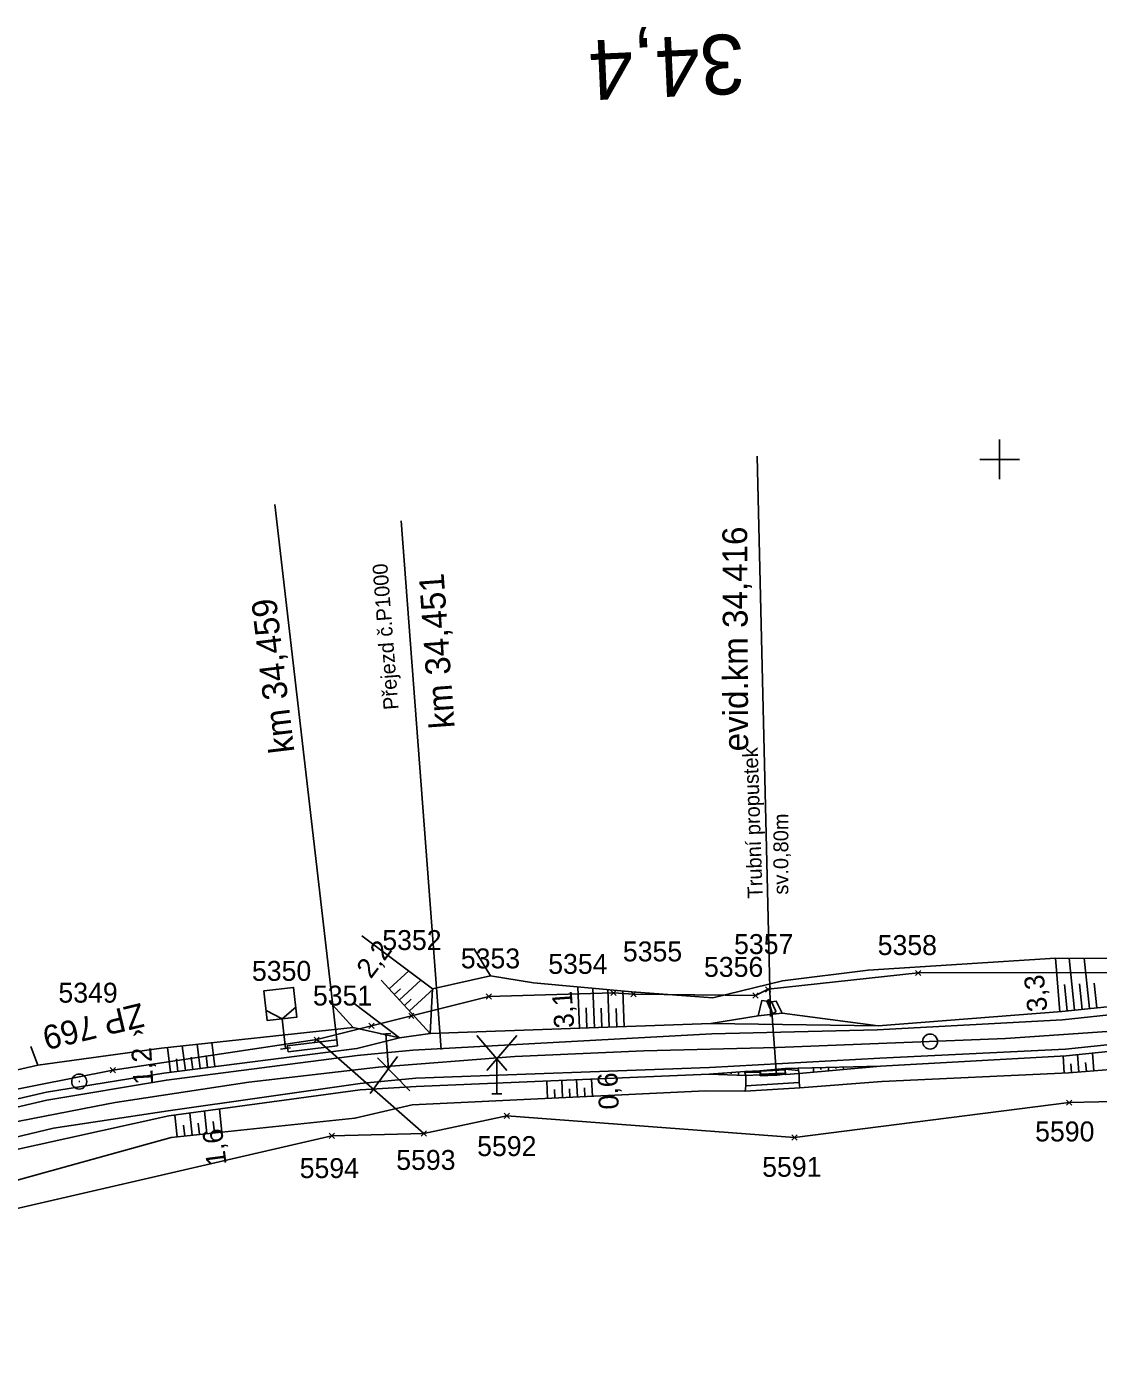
# Model space of a CAD drawing. Extents: x -805730 to -804640, y -1150889 to -1150366.
# Drawn here: x -805297.6 to -805190.1, y -1150691.7 to -1150556.6 of the extents above; entities that cross this region are included whole.
import ezdxf

# ---------------------------------------------------------------- set-up
doc = ezdxf.new("R2010")
doc.units = 0
for name, color, linetype in [('0381KM032-037P - Vrstva 1', 7, 'Continuous'), ('0381KM032-037P - Vrstva 17', 7, 'Continuous'), ('0381KM032-037P - Vrstva 19', 7, 'Continuous'), ('0381KM032-037P - Vrstva 4', 7, 'Continuous'), ('0381KM032-037P - Vrstva 48', 7, 'Continuous'), ('0381KM032-037P - Vrstva 49', 7, 'Continuous'), ('0381KM032-037P - Vrstva 51', 7, 'Continuous'), ('0381KM032-037P - Vrstva 55', 7, 'Continuous'), ('0381KM032-037P - Vrstva 7', 7, 'Continuous'), ('0381KM032-037P - Vrstva 9', 7, 'Continuous'), ('krizky_1000 - Vrstva 1', 7, 'Continuous'), ('szdc - hran DP', 7, 'Continuous'), ('szdc - szdc_cislo', 7, 'Continuous'), ('szdc - szdc_krizek', 7, 'Continuous'), ('vyt_sit - ohrožené', 7, 'Continuous')]:
    doc.layers.add(name, color=color, linetype=linetype)

msp = doc.modelspace()

# ---------------------------------------------------------------- linework, layer by layer
at = {"layer": '0381KM032-037P - Vrstva 1'}
for points in [[(-805182.79, -1150656.72), (-805189.2, -1150657.4), (-805199.42, -1150658.12), (-805222.35, -1150659), (-805235.71, -1150659.34), (-805248.65, -1150659.92), (-805262.34, -1150660.99)], [(-805262.34, -1150660.99), (-805275.34, -1150662.5), (-805288.75, -1150664.54), (-805289.64, -1150664.68), (-805304.6, -1150667.62), (-805306.42, -1150668.06)]]:
    msp.add_lwpolyline(points, dxfattribs=at)
at = {"layer": '0381KM032-037P - Vrstva 17'}
for points in [[(-805070.8, -1150598.9), (-805121.06, -1150638.84), (-805152.76, -1150646.7), (-805170.92, -1150650.08), (-805194.39, -1150650.05), (-805213.2, -1150651.26), (-805221.79, -1150652.33), (-805228.79, -1150654.03)], [(-805228.79, -1150654.03), (-805236.91, -1150653.41), (-805246.77, -1150652.51), (-805251.08, -1150651.83), (-805252.77, -1150649.08)], [(-805266.94, -1150654.72), (-805264.88, -1150657), (-805284.09, -1150659.06), (-805296.52, -1150660.78), (-805297.22, -1150658.9)]]:
    msp.add_lwpolyline(points, dxfattribs=at)
at = {"layer": '0381KM032-037P - Vrstva 19'}
for p, q in [((-805224.33, -1150599.68), (-805223.01, -1150655.91)), ((-805222.9, -1150655.44), (-805223.36, -1150654.35)), ((-805222.89, -1150654.41), (-805222.49, -1150655.3)), ((-805223.99, -1150661.38), (-805221.54, -1150661.24)), ((-805221.51, -1150661.18), (-805221.49, -1150661.72)), ((-805225.47, -1150661.83), (-805224.04, -1150661.74)), ((-805224.04, -1150661.49), (-805224.04, -1150661.74)), ((-805221.51, -1150661.6), (-805224, -1150661.7)), ((-805224, -1150661.7), (-805224, -1150661.8)), ((-805224, -1150661.8), (-805221.51, -1150661.7)), ((-805221.51, -1150661.7), (-805221.51, -1150661.6))]:
    msp.add_line(p, q, dxfattribs=at)
msp.add_lwpolyline([(-805224.22, -1150655.82), (-805223.87, -1150654.3), (-805223.36, -1150654.35), (-805223.23, -1150654.21), (-805222.89, -1150654.41), (-805222.41, -1150654.36), (-805221.82, -1150655.55)], close=True, dxfattribs=at)
for points in [[(-805223.23, -1150654.21), (-805222.87, -1150655.41), (-805222.4, -1150661.78)], [(-805225.57, -1150661.42), (-805224.05, -1150661.35), (-805223.99, -1150661.38)], [(-805225.56, -1150661.53), (-805224.04, -1150661.49), (-805224.05, -1150661.35)], [(-805221.51, -1150661.7), (-805221.51, -1150661.69), (-805221.54, -1150661.24), (-805221.52, -1150661.12), (-805220.23, -1150661.07), (-805220.19, -1150661.33), (-805220.13, -1150661.62)], [(-805220.19, -1150661.33), (-805221.51, -1150661.18), (-805221.52, -1150661.12)], [(-805225.57, -1150661.42), (-805225.56, -1150661.53), (-805225.47, -1150661.83), (-805225.46, -1150662.84), (-805225.54, -1150663.4), (-805220.04, -1150663.05), (-805220.11, -1150662.52), (-805225.46, -1150662.84)], [(-805224, -1150661.7), (-805224.04, -1150661.74), (-805224.02, -1150661.84), (-805223.26, -1150661.81), (-805222.4, -1150661.78)], [(-805223.99, -1150661.81), (-805224, -1150661.8)], [(-805223.99, -1150661.38), (-805223.99, -1150661.81), (-805221.51, -1150661.69)], [(-805222.4, -1150661.78), (-805221.56, -1150661.7), (-805221.49, -1150661.72)], [(-805220.11, -1150662.52), (-805220.13, -1150661.62), (-805221.49, -1150661.72), (-805221.51, -1150661.6)]]:
    msp.add_lwpolyline(points, dxfattribs=at)
for centre, major_axis, ratio, start_param, end_param in [((-805222.69, -1150655.38), (0.215, 0.047), 0.800066, 3.235081, 6.495155), ((-805222.47, -1150661.77), (-0.4, -0.017), 0.197294, 3.17264, 6.315874), ((-805222.47, -1150661.77), (0.4, 0.019), 0.014453, 3.164337, 6.322931)]:
    msp.add_ellipse(centre, major_axis=major_axis, ratio=ratio, start_param=start_param, end_param=end_param, dxfattribs=at)
at = {"layer": '0381KM032-037P - Vrstva 4'}
for p, q in [((-805260.04, -1150606.16), (-805256.03, -1150659.22)), ((-805261.09, -1150657.61), (-805262.09, -1150657.68)), ((-805261.59, -1150657.65), (-805261.34, -1150661.14)), ((-805252.46, -1150657.82), (-805249.46, -1150661.32)), ((-805251.46, -1150661.32), (-805248.46, -1150657.82)), ((-805260.43, -1150659.92), (-805263.17, -1150663.62)), ((-805262.34, -1150660.99), (-805248.65, -1150659.92)), ((-805259.18, -1150663.34), (-805262.42, -1150660.06)), ((-805250.46, -1150663.67), (-805250.46, -1150660.17)), ((-805250.96, -1150663.67), (-805249.96, -1150663.67))]:
    msp.add_line(p, q, dxfattribs=at)
for points in [[(-805097.6, -1150634.39), (-805112.1, -1150639.75), (-805119.36, -1150642.27), (-805152.08, -1150650.89), (-805169.94, -1150653.7), (-805193.71, -1150656.24), (-805212.28, -1150657.22)], [(-805096.44, -1150637.01), (-805110.9, -1150642.46), (-805118.26, -1150644.98), (-805151.42, -1150653.61), (-805169.41, -1150656.67), (-805193.4, -1150659.17), (-805212.01, -1150660.08)], [(-805134.98, -1150644.55), (-805152.23, -1150649.93), (-805170.06, -1150652.94), (-805193.76, -1150655.4), (-805212.2, -1150656.84), (-805228.99, -1150656.61)], [(-805134.56, -1150650.98), (-805151.31, -1150654.12), (-805169.36, -1150657.36), (-805193.31, -1150659.84), (-805211.96, -1150660.88), (-805220.23, -1150661.07)], [(-805228.99, -1150656.61), (-805257.13, -1150657.62), (-805260.23, -1150658.03), (-805264.49, -1150659.11), (-805283.86, -1150661.58), (-805295.64, -1150663.5), (-805324.06, -1150670.09), (-805365.63, -1150680.4), (-805372.09, -1150681.89), (-805381.91, -1150683.24), (-805417.14, -1150687.42), (-805420, -1150686.97)], [(-805212.28, -1150657.22), (-805228.89, -1150657.63), (-805258.88, -1150659.27), (-805264.46, -1150659.8), (-805283.61, -1150662.28), (-805295.6, -1150664.3), (-805323.97, -1150670.91), (-805365.39, -1150681.52), (-805371.9, -1150683.14), (-805381.67, -1150685.01), (-805417.27, -1150688.09), (-805420, -1150686.97)], [(-805212.01, -1150660.08), (-805229.13, -1150661), (-805258.58, -1150662.1), (-805264.18, -1150662.62), (-805283.43, -1150665.36), (-805294.93, -1150667.11), (-805323.21, -1150673.86), (-805364.72, -1150684.28), (-805371.95, -1150685.67), (-805381.73, -1150687.49), (-805401.63, -1150689.36), (-805419.33, -1150691.07), (-805419.49, -1150691.68)], [(-805225.57, -1150661.42), (-805229.16, -1150661.68), (-805258.55, -1150662.93), (-805264.16, -1150663.27), (-805283.37, -1150665.88), (-805323.33, -1150674.68), (-805364.37, -1150685.33), (-805371.95, -1150687.26), (-805381.71, -1150688.97), (-805419.49, -1150691.68)]]:
    msp.add_lwpolyline(points, dxfattribs=at)
at = {"layer": '0381KM032-037P - Vrstva 48'}
for p, q in [((-805193.97, -1150655.42), (-805194.39, -1150650.05)), ((-805192.48, -1150655.27), (-805193.02, -1150650.05)), ((-805190.99, -1150655.11), (-805191.51, -1150650.05)), ((-805261.25, -1150653.12), (-805259.3, -1150651.33)), ((-805260.75, -1150653.68), (-805260.13, -1150653.11)), ((-805260.24, -1150654.23), (-805258.08, -1150652.25)), ((-805259.22, -1150655.33), (-805256.81, -1150653.11)), ((-805242.17, -1150657.08), (-805242.32, -1150652.92)), ((-805240.67, -1150657.03), (-805240.81, -1150653.06)), ((-805239.17, -1150656.98), (-805239.31, -1150653.2)), ((-805193.23, -1150655.34), (-805193.5, -1150652.7)), ((-805191.73, -1150655.19), (-805192, -1150652.62)), ((-805190.24, -1150655.03), (-805190.5, -1150652.54)), ((-805259.73, -1150654.78), (-805259.05, -1150654.16)), ((-805237.67, -1150656.92), (-805237.8, -1150653.33)), ((-805241.42, -1150657.06), (-805241.49, -1150655.02)), ((-805239.92, -1150657), (-805239.99, -1150655.06)), ((-805238.42, -1150656.95), (-805238.49, -1150655.11)), ((-805278.74, -1150660.93), (-805279.04, -1150658.52)), ((-805283.2, -1150661.49), (-805283.52, -1150659)), ((-805281.71, -1150661.3), (-805282.03, -1150658.84)), ((-805280.97, -1150661.21), (-805281.12, -1150659.98)), ((-805280.22, -1150661.11), (-805280.54, -1150658.68)), ((-805279.48, -1150661.02), (-805279.64, -1150659.81)), ((-805193.54, -1150661.57), (-805193.62, -1150659.86)), ((-805192.05, -1150661.47), (-805192.19, -1150659.72)), ((-805190.55, -1150661.35), (-805190.69, -1150659.57)), ((-805282.46, -1150661.4), (-805282.61, -1150660.16)), ((-805218.69, -1150661.03), (-805218.68, -1150661.49)), ((-805217.94, -1150661.02), (-805217.94, -1150661.22)), ((-805217.19, -1150661), (-805217.18, -1150661.35)), ((-805216.44, -1150660.98), (-805216.44, -1150661.13)), ((-805215.69, -1150660.96), (-805215.68, -1150661.22)), ((-805192.79, -1150661.53), (-805192.86, -1150660.66)), ((-805191.3, -1150661.41), (-805191.37, -1150660.53)), ((-805245.37, -1150664.11), (-805245.45, -1150662.37)), ((-805243.87, -1150664.03), (-805243.95, -1150662.31)), ((-805242.37, -1150663.96), (-805242.45, -1150662.25)), ((-805240.87, -1150663.89), (-805240.95, -1150662.18)), ((-805227.71, -1150661.57), (-805227.7, -1150661.74)), ((-805226.96, -1150661.52), (-805226.95, -1150661.64)), ((-805226.21, -1150661.47), (-805226.19, -1150661.8)), ((-805244.62, -1150664.07), (-805244.66, -1150663.21)), ((-805243.12, -1150664), (-805243.16, -1150663.14)), ((-805241.62, -1150663.93), (-805241.66, -1150663.07)), ((-805279.55, -1150667.65), (-805279.78, -1150665.39)), ((-805278.05, -1150667.5), (-805278.3, -1150665.19)), ((-805282.53, -1150667.97), (-805282.76, -1150665.8)), ((-805281.04, -1150667.81), (-805281.27, -1150665.6)), ((-805280.29, -1150667.73), (-805280.41, -1150666.61)), ((-805278.8, -1150667.58), (-805278.92, -1150666.44)), ((-805281.78, -1150667.89), (-805281.9, -1150666.79))]:
    msp.add_line(p, q, dxfattribs=at)
at = {"layer": '0381KM032-037P - Vrstva 49'}
for p, q in [((-805257.13, -1150657.62), (-805262.06, -1150652.24)), ((-805256.9, -1150653.13), (-805257.13, -1150657.62)), ((-805220.23, -1150661.07), (-805211.96, -1150660.88)), ((-805224.04, -1150661.74), (-805225.47, -1150661.83))]:
    msp.add_line(p, q, dxfattribs=at)
for points in [[(-805070.8, -1150598.9), (-805121.06, -1150638.84), (-805152.76, -1150646.7), (-805170.92, -1150650.08), (-805194.39, -1150650.05), (-805213.2, -1150651.26), (-805221.79, -1150652.33), (-805228.79, -1150654.03)], [(-805134.98, -1150644.55), (-805152.23, -1150649.93), (-805170.06, -1150652.94), (-805193.76, -1150655.4), (-805212.2, -1150656.84), (-805221.82, -1150655.55)], [(-805228.79, -1150654.03), (-805236.91, -1150653.41), (-805246.77, -1150652.51), (-805251.08, -1150651.83), (-805256.9, -1150653.13), (-805263.99, -1150647.81)], [(-805134.43, -1150652.2), (-805150.83, -1150656.03), (-805168.82, -1150659.61), (-805193.05, -1150661.55), (-805211.83, -1150662.42), (-805220.04, -1150663.05)], [(-805151.31, -1150654.12), (-805169.36, -1150657.36), (-805193.31, -1150659.84), (-805211.96, -1150660.88), (-805220.13, -1150661.62)], [(-805221.82, -1150655.55), (-805224.22, -1150655.82), (-805228.99, -1150656.61), (-805257.13, -1150657.62)], [(-805296.52, -1150660.78), (-805284.09, -1150659.06), (-805264.88, -1150657), (-805260.23, -1150658.03)], [(-805257.13, -1150657.62), (-805260.23, -1150658.03), (-805264.49, -1150659.11)], [(-805420, -1150686.97), (-805417.14, -1150687.42), (-805381.91, -1150683.24), (-805372.09, -1150681.89), (-805365.63, -1150680.4), (-805324.06, -1150670.09), (-805295.64, -1150663.5), (-805283.86, -1150661.58), (-805264.49, -1150659.11)], [(-805296.52, -1150660.78), (-805324.89, -1150667.28), (-805344.39, -1150673.21)], [(-805220.23, -1150661.07), (-805221.52, -1150661.12), (-805224.05, -1150661.35), (-805225.57, -1150661.42), (-805229.16, -1150661.68)], [(-805372.13, -1150688.5), (-805323.33, -1150674.68), (-805283.37, -1150665.88), (-805264.16, -1150663.27), (-805258.55, -1150662.93), (-805229.16, -1150661.68), (-805225.47, -1150661.83)], [(-805224.04, -1150661.74), (-805224.02, -1150661.84), (-805223.26, -1150661.81), (-805222.4, -1150661.78), (-805221.56, -1150661.7)], [(-805221.56, -1150661.7), (-805221.49, -1150661.72), (-805220.13, -1150661.62)], [(-805229.52, -1150663.36), (-805258.94, -1150664.75), (-805264.69, -1150666.1), (-805283.13, -1150668.03), (-805332.88, -1150681.81), (-805363.18, -1150690.85)], [(-805229.52, -1150663.36), (-805225.54, -1150663.4), (-805220.04, -1150663.05)]]:
    msp.add_lwpolyline(points, dxfattribs=at)
at = {"layer": '0381KM032-037P - Vrstva 51'}
msp.add_line((-805264.77, -1150654.58), (-805260.23, -1150658.03), dxfattribs=at)
msp.add_lwpolyline([(-805262.06, -1150652.24), (-805257.13, -1150657.62), (-805260.23, -1150658.03)], dxfattribs=at)
at = {"layer": '0381KM032-037P - Vrstva 55'}
msp.add_line((-805268.53, -1150658.22), (-805257.77, -1150667.64), dxfattribs=at)
at = {"layer": '0381KM032-037P - Vrstva 7'}
for p, q in [((-805272, -1150656.13), (-805271.65, -1150659.11)), ((-805272.15, -1150659.17), (-805271.16, -1150659.05))]:
    msp.add_line(p, q, dxfattribs=at)
for points in [[(-805272, -1150656.13), (-805270.51, -1150655.96), (-805270.85, -1150652.98), (-805273.83, -1150653.32), (-805273.49, -1150656.3), (-805272, -1150656.13)], [(-805273.6, -1150655.31), (-805272, -1150656.13), (-805270.62, -1150654.96)]]:
    msp.add_lwpolyline(points, dxfattribs=at)
msp.add_circle((-805206.98, -1150658.41), 0.75, dxfattribs=at)
at = {"layer": '0381KM032-037P - Vrstva 9'}
for p, q in [((-805266.48, -1150658.55), (-805272.73, -1150604.53)), ((-805266.52, -1150658.25), (-805271.48, -1150658.85)), ((-805266.52, -1150658.25), (-805266.59, -1150657.67)), ((-805266.45, -1150658.84), (-805266.52, -1150658.25)), ((-805271.48, -1150658.85), (-805271.41, -1150659.44)), ((-805271.41, -1150659.44), (-805266.45, -1150658.84))]:
    msp.add_line(p, q, dxfattribs=at)
at = {"layer": 'krizky_1000 - Vrstva 1'}
for points in [[(-805200, -1150598), (-805200, -1150602)], [(-805202, -1150600), (-805198, -1150600)]]:
    msp.add_lwpolyline(points, dxfattribs=at)
at = {"layer": 'szdc - hran DP'}
for p, q in [((-805223.22, -1150653.17), (-805208.17, -1150651.53)), ((-805208.17, -1150651.53), (-805178.93, -1150651.45)), ((-805224.51, -1150653.79), (-805223.22, -1150653.17)), ((-805259.03, -1150655.84), (-805251.25, -1150653.89)), ((-805251.25, -1150653.89), (-805238.75, -1150653.54)), ((-805238.75, -1150653.54), (-805236.73, -1150653.66)), ((-805236.73, -1150653.66), (-805224.51, -1150653.79)), ((-805263.04, -1150656.84), (-805259.03, -1150655.84)), ((-805268.53, -1150658.22), (-805263.04, -1150656.84)), ((-805288.99, -1150661.29), (-805268.53, -1150658.22)), ((-805313.93, -1150666.21), (-805288.99, -1150661.29)), ((-805161.69, -1150663.73), (-805193.03, -1150664.54)), ((-805193.03, -1150664.54), (-805220.59, -1150668.04)), ((-805249.45, -1150665.86), (-805257.77, -1150667.64)), ((-805220.59, -1150668.04), (-805249.45, -1150665.86)), ((-805267.02, -1150667.87), (-805308.19, -1150677.39)), ((-805257.77, -1150667.64), (-805267.02, -1150667.87))]:
    msp.add_line(p, q, dxfattribs=at)
at = {"layer": 'szdc - szdc_krizek'}
for p, q in [((-805207.91, -1150651.79), (-805208.44, -1150651.27)), ((-805208.44, -1150651.79), (-805207.91, -1150651.27)), ((-805222.96, -1150653.44), (-805223.49, -1150652.91)), ((-805223.49, -1150653.44), (-805222.96, -1150652.91)), ((-805250.98, -1150654.16), (-805251.52, -1150653.62)), ((-805251.52, -1150654.16), (-805250.98, -1150653.62)), ((-805238.48, -1150653.8), (-805239.02, -1150653.28)), ((-805239.02, -1150653.8), (-805238.48, -1150653.28)), ((-805236.46, -1150653.93), (-805237, -1150653.4)), ((-805237, -1150653.93), (-805236.46, -1150653.4)), ((-805224.24, -1150654.05), (-805224.78, -1150653.53)), ((-805224.78, -1150654.05), (-805224.24, -1150653.53)), ((-805258.77, -1150656.1), (-805259.3, -1150655.57)), ((-805259.3, -1150656.1), (-805258.77, -1150655.57)), ((-805262.78, -1150657.1), (-805263.31, -1150656.57)), ((-805263.31, -1150657.1), (-805262.78, -1150656.57)), ((-805268.27, -1150658.49), (-805268.8, -1150657.96)), ((-805268.8, -1150658.49), (-805268.27, -1150657.96)), ((-805288.72, -1150661.55), (-805289.26, -1150661.03)), ((-805289.26, -1150661.55), (-805288.72, -1150661.03)), ((-805192.77, -1150664.8), (-805193.3, -1150664.28)), ((-805193.3, -1150664.8), (-805192.77, -1150664.28)), ((-805249.19, -1150666.12), (-805249.72, -1150665.59)), ((-805249.72, -1150666.12), (-805249.19, -1150665.59)), ((-805266.76, -1150668.14), (-805267.29, -1150667.6)), ((-805267.29, -1150668.14), (-805266.76, -1150667.6)), ((-805257.51, -1150667.91), (-805258.04, -1150667.38)), ((-805258.04, -1150667.91), (-805257.51, -1150667.38)), ((-805220.33, -1150668.3), (-805220.86, -1150667.78)), ((-805220.86, -1150668.3), (-805220.33, -1150667.78))]:
    msp.add_line(p, q, dxfattribs=at)
at = {"layer": 'vyt_sit - ohrožené'}
msp.add_line((-805292.41, -1150662.43), (-805292.31, -1150662.43), dxfattribs=at)
msp.add_circle((-805292.36, -1150662.43), 0.756, dxfattribs=at)

# ---------------------------------------------------------------- texts
at = {"layer": '0381KM032-037P - Vrstva 19'}
for s, height, rotation, p in [('evid.km 34,416', 2.4868, 90.2833, (-805225.23, -1150629.29)), ('Trubní propustek', 1.4998, 91.9626, (-805223.77, -1150644.03)), ('sv.0,80m', 1.5, 89.9669, (-805221.21, -1150643.67))]:
    msp.add_text(s, height=height, rotation=rotation, dxfattribs=at).set_placement(p)
at = {"layer": '0381KM032-037P - Vrstva 4'}
for s, height, rotation, p in [('Přejezd č.P1000', 1.5, 94.4666, (-805260.31, -1150625.07)), ('km 34,451', 2.5, 94.1036, (-805254.68, -1150626.93))]:
    msp.add_text(s, height=height, rotation=rotation, dxfattribs=at).set_placement(p)
at = {"layer": '0381KM032-037P - Vrstva 48'}
for s, rotation, p in [('2,2', 53.0616, (-805263.1, -1150652.2)), ('3,3', 95.9333, (-805195.2, -1150655.32)), ('3,1', 94.1143, (-805242.68, -1150657)), ('1,2', 93.2392, (-805284.93, -1150662.67)), ('0,6', 92.4516, (-805238.21, -1150665.19)), ('1,6', 97.414, (-805277.56, -1150670.74))]:
    msp.add_text(s, height=2, rotation=rotation, dxfattribs=at).set_placement(p)
at = {"layer": '0381KM032-037P - Vrstva 7'}
msp.add_text('34,4', height=6, rotation=182.5512, dxfattribs=at).set_placement((-805225.74, -1150557.29))
at = {"layer": '0381KM032-037P - Vrstva 9'}
msp.add_text('km 34,459', height=2.5, rotation=96.8511, dxfattribs=at).set_placement((-805270.76, -1150629.34))
at = {"layer": 'szdc - szdc_cislo'}
for s, p in [('5352', (-805261.95, -1150649.23)), ('5357', (-805226.65, -1150649.63)), ('5358', (-805212.24, -1150649.73)), ('5353', (-805254.07, -1150651.07)), ('5355', (-805237.81, -1150650.37)), ('5350', (-805275.03, -1150652.32)), ('5354', (-805245.3, -1150651.62)), ('5356', (-805229.67, -1150651.92)), ('5349', (-805294.45, -1150654.51)), ('5351', (-805268.91, -1150654.8)), ('5590', (-805196.44, -1150668.43)), ('5592', (-805252.43, -1150669.9)), ('5593', (-805260.55, -1150671.29)), ('5594', (-805270.24, -1150672.11)), ('5591', (-805223.83, -1150671.98))]:
    msp.add_text(s, height=2, dxfattribs=at).set_placement(p)
at = {"layer": 'vyt_sit - ohrožené'}
msp.add_text('ŽP 769', height=2.4, rotation=193.6062, dxfattribs=at).set_placement((-805286.16, -1150654.52))

doc.saveas('drawing.dxf')
